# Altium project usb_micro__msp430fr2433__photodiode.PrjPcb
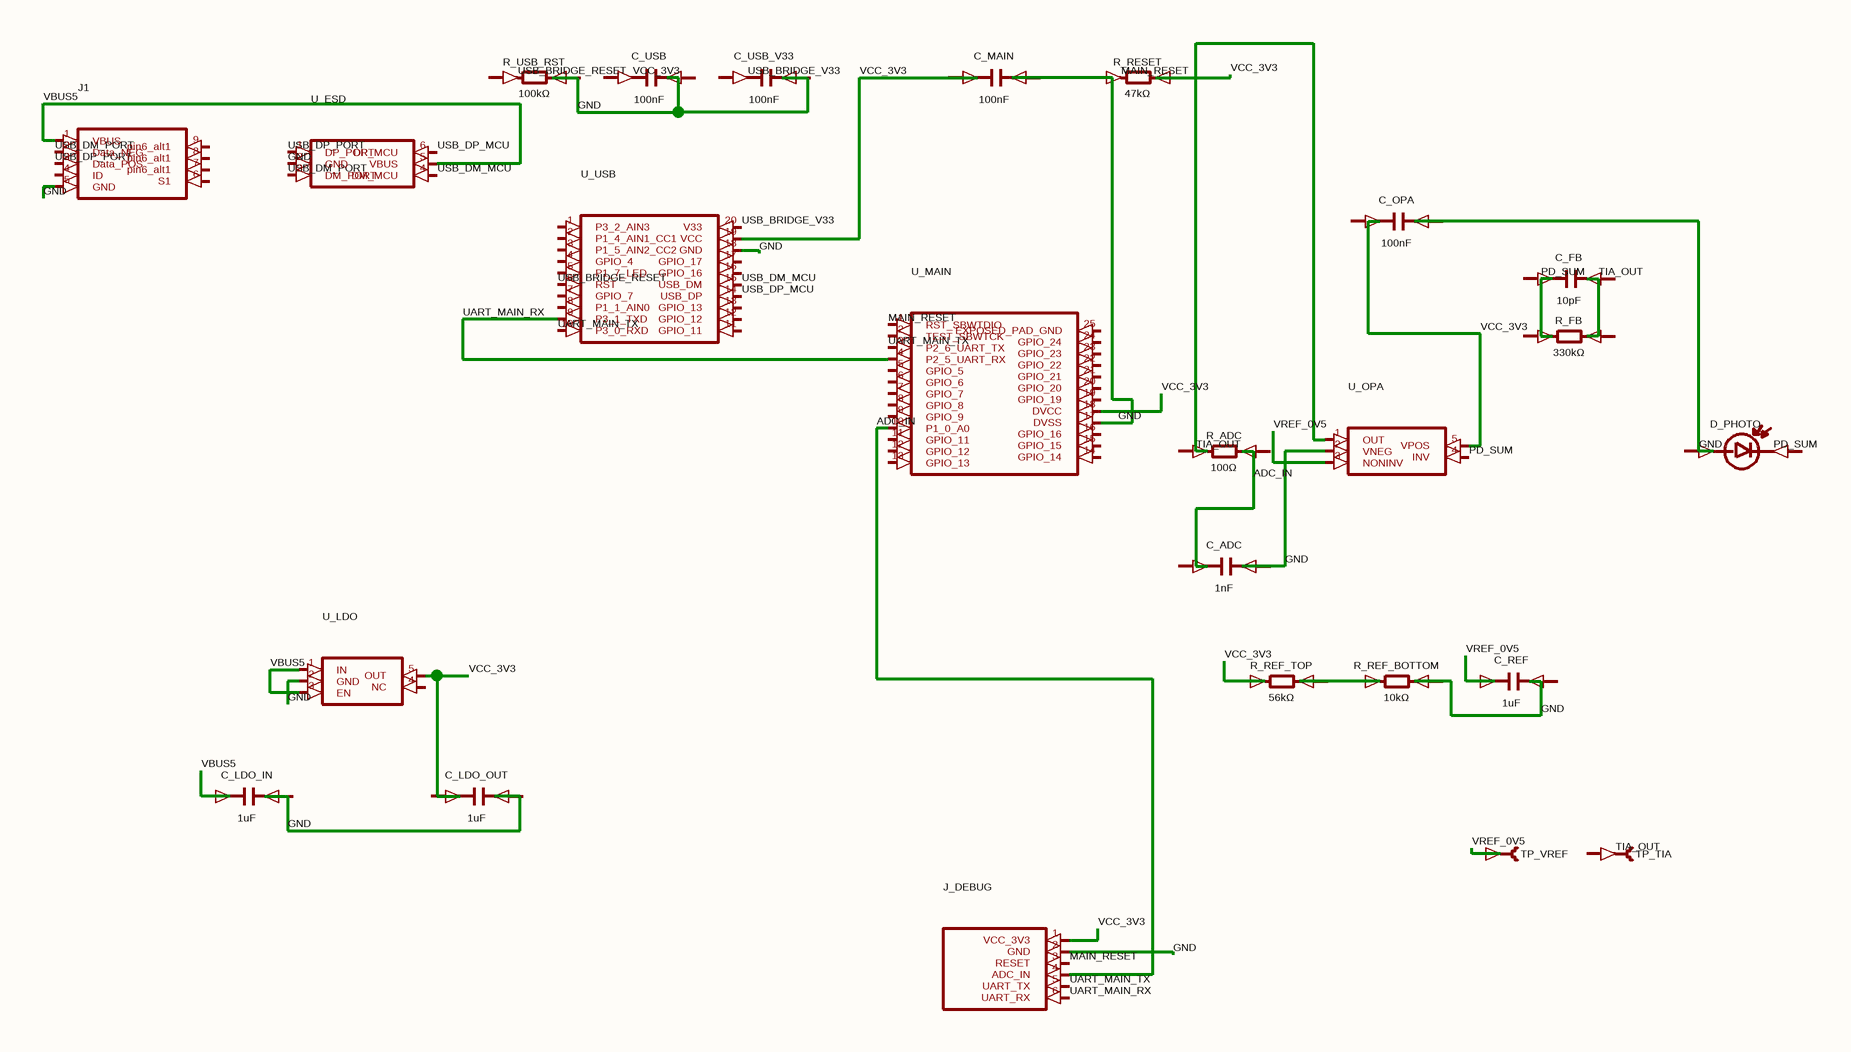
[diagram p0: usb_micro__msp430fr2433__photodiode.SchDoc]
1 sheet, 25 parts. Net scope: global (net labels, ports and power ports of the same name join across sheets).
Board file: usb_micro__msp430fr2433__photodiode.PcbDoc

## Sheet usb_micro__msp430fr2433__photodiode.SchDoc
size 208 x 135 mm

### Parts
C_ADC  1nF
C_FB  10pF
C_LDO_IN  1uF
C_LDO_OUT  1uF
C_MAIN  100nF
C_OPA  100nF
C_REF  1uF
C_USB  100nF
C_USB_V33  100nF
D_PHOTO  (no value)
J1  (no value)
J_DEBUG  (no value)
R_ADC  100Ω
R_FB  330kΩ
R_REF_BOTTOM  10kΩ
R_REF_TOP  56kΩ
R_RESET  47kΩ
R_USB_RST  100kΩ
TP_TIA  (no value)
TP_VREF  (no value)
U_ESD  (no value)
U_LDO  (no value)
U_MAIN  (no value)
U_OPA  (no value)
U_USB  (no value)

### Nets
ADC_IN: J_DEBUG.4(ADC_IN) U_MAIN.10(P1_0_A0)
GND: C_ADC.2(neg) C_LDO_IN.1(pos) C_MAIN.2(neg) C_OPA.2(neg) J1.1(VBUS) J1.5(GND) J_DEBUG.2(GND) R_REF_BOTTOM.2(cathode) R_RESET.1(anode) U_ESD.2(GND) U_ESD.5(VBUS) U_LDO.1(IN) U_LDO.2(GND) U_LDO.3(EN) U_MAIN.17(DVSS) U_OPA.2(VNEG) U_USB.18(GND)  [also labelled VBUS5]
MAIN_RESET: J_DEBUG.3(RESET) U_MAIN.1(RST_SBWTDIO)
PD_SUM: U_OPA.4(INV)
TIA_OUT: C_MAIN.1(pos) J_DEBUG.1(VCC_3V3) R_REF_TOP.1(anode) R_RESET.2(cathode) U_LDO.5(OUT) U_MAIN.18(DVCC) U_OPA.1(OUT) U_OPA.5(VPOS) U_USB.19(VCC)  [also labelled VCC_3V3]
UART_MAIN_RX: J_DEBUG.6(UART_RX) U_MAIN.4(P2_5_UART_RX) U_USB.9(P3_1_TXD)
UART_MAIN_TX: J_DEBUG.5(UART_TX) U_MAIN.3(P2_6_UART_TX) U_USB.10(P3_0_RXD)
USB_BRIDGE_RESET: U_USB.6(RST)
USB_BRIDGE_V33: U_USB.20(V33)
USB_DM_MCU: U_ESD.4(DM_MCU) U_USB.15(USB_DM)
USB_DM_PORT: J1.2(Data_NEG) U_ESD.3(DM_PORT)
USB_DP_MCU: U_ESD.6(DP_MCU) U_USB.14(USB_DP)
USB_DP_PORT: J1.3(Data_POS) U_ESD.1(DP_PORT)
VREF_0V5: C_REF.1(pos) TP_VREF.1(pin1) U_OPA.3(NONINV)
NetR_REF_BOTTOM_1: R_REF_BOTTOM.1(anode) R_REF_TOP.2(cathode)

Not connected (* = marked no-connect by the designer): C_ADC 1(pos); C_FB 1(pos) 2(neg); C_LDO_IN 2(neg); C_LDO_OUT 1(pos) 2(neg); C_OPA 1(pos); C_REF 2(neg); C_USB 1(pos) 2(neg); C_USB_V33 1(pos) 2(neg); D_PHOTO 1(anode) 2(cathode); J1 4(ID) 6(S1) 7(pin6_alt1) 8(pin6_alt1) 9(pin6_alt1); R_ADC 1(anode) 2(cathode); R_FB 1(anode) 2(cathode); R_USB_RST 1(anode) 2(cathode); TP_TIA 1(pin1); U_LDO 4(NC); U_MAIN 2(TEST_SBWTCK) 5(GPIO_5) 6(GPIO_6) 7(GPIO_7) 8(GPIO_8) 9(GPIO_9) 11(GPIO_11) 12(GPIO_12) 13(GPIO_13) 14(GPIO_14) 15(GPIO_15) 16(GPIO_16) 19(GPIO_19) 20(GPIO_20) 21(GPIO_21) 22(GPIO_22) 23(GPIO_23) 24(GPIO_24) 25(EXPOSED_PAD_GND); U_USB 1(P3_2_AIN3) 2(P1_4_AIN1_CC1) 3(P1_5_AIN2_CC2) 4(GPIO_4) 5(P1_7_LED) 7(GPIO_7) 8(P1_1_AIN0) 11(GPIO_11) 12(GPIO_12) 13(GPIO_13) 16(GPIO_16) 17(GPIO_17)

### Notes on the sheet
- Labels drawn without touching a wire or pin: MAIN_RESET, PD_SUM, TIA_OUT, USB_BRIDGE_RESET, USB_BRIDGE_V33, VCC_3V3

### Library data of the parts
C_ADC C_FB C_LDO_IN C_LDO_OUT C_MAIN C_OPA C_REF C_USB C_USB_V33 = capacitor_right
D_PHOTO = photodiode_horz
J1 = J1
J_DEBUG = J_DEBUG
R_ADC R_FB R_REF_BOTTOM R_REF_TOP R_RESET R_USB_RST = boxresistor_right
TP_TIA TP_VREF = testpoint_right
U_ESD = U_ESD
U_LDO = U_LDO
U_MAIN = U_MAIN
U_OPA = U_OPA
U_USB = U_USB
